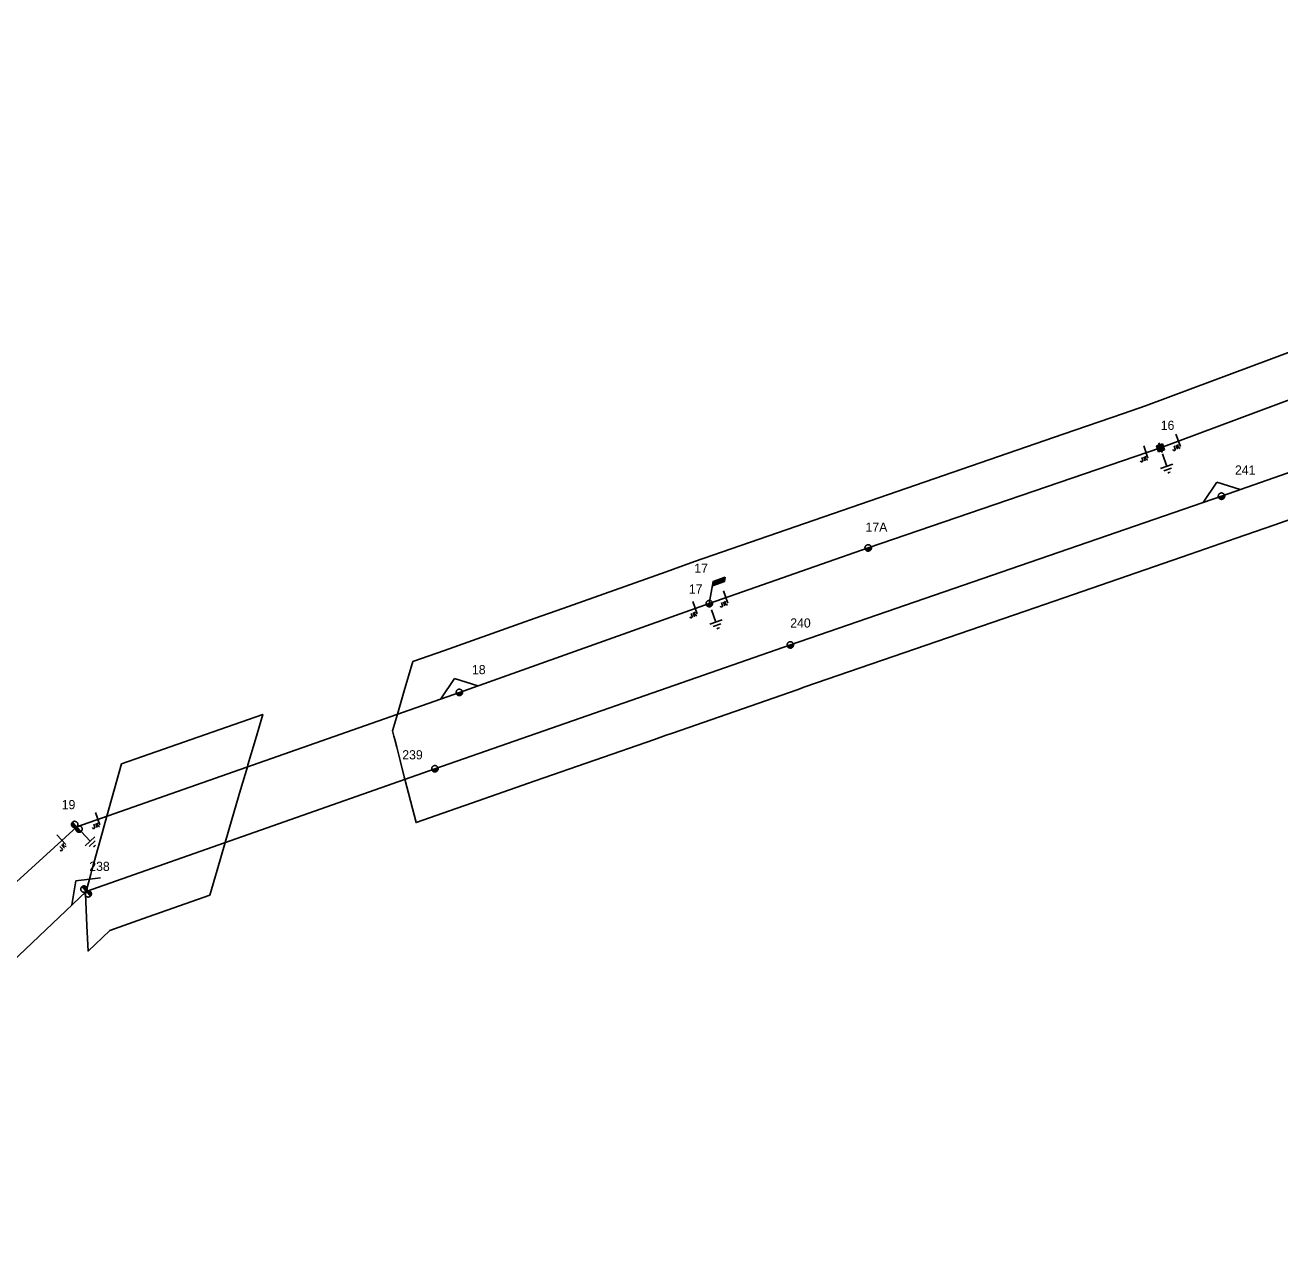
# Model space of a CAD drawing. Extents: x -540879 to -537255, y -1184046 to -1180016.
# Drawn here: x -539234.9 to -538995.4, y -1180859 to -1180626.1 of the extents above; entities that cross this region are included whole.
import ezdxf

# ---------------------------------------------------------------- set-up
doc = ezdxf.new("R2010")
doc.units = 0
for name, color, linetype in [('Default', 7, 'Continuous'), ('Vrstva 1', 7, 'Continuous'), ('Vrstva 11', 7, 'Continuous'), ('Vrstva 12', 7, 'Continuous'), ('Vrstva 13', 7, 'Continuous'), ('Vrstva 14', 7, 'Continuous'), ('Vrstva 15', 7, 'Continuous'), ('Vrstva 18', 7, 'Continuous'), ('Vrstva 2', 7, 'Continuous'), ('Vrstva 35', 7, 'Continuous')]:
    doc.layers.add(name, color=color, linetype=linetype)

# ---------------------------------------------------------------- blocks, each defined once
blk = doc.blocks.new('VN840')
at = {"layer": 'Vrstva 15'}
for points in [[(-0.01, 1.41), (-0.01, -1.09)], [(-1.51, -1.24), (-1.51, -1.15)], [(-1.48, -1.35), (-1.51, -1.24)], [(-1.33, -1.42), (-1.48, -1.35)], [(-1.27, -1.42), (-1.33, -1.42)], [(-1.13, -1.35), (-1.27, -1.42)], [(-1.09, -1.24), (-1.13, -1.35)], [(-1.09, -0.59), (-1.09, -1.24)], [(-0.68, -0.59), (-0.68, -1.42)], [(-0.68, -1.11), (-0.27, -0.59)], [(-0.54, -0.94), (-0.2, -1.42)]]:
    blk.add_lwpolyline(points, dxfattribs=at)
blk = doc.blocks.new('VN860')
at = {"layer": 'Vrstva 15'}
for points in [[(-3.74, 0), (0.01, 2.82)], [(0.01, 2.82), (3.76, 0)]]:
    blk.add_lwpolyline(points, dxfattribs=at)
blk = doc.blocks.new('VN440')
at = {"layer": 'Vrstva 2'}
for points in [[(1.22, 0), (1.21, 0.13), (1.19, 0.25), (1.16, 0.38), (1.11, 0.5), (1.05, 0.61), (0.98, 0.72), (0.9, 0.82), (0.81, 0.91), (0.71, 0.99), (0.6, 1.06), (0.49, 1.12), (0.37, 1.16), (0.25, 1.2), (0.12, 1.22), (-0.01, 1.22), (-0.14, 1.22), (-0.26, 1.2), (-0.39, 1.16), (-0.51, 1.12), (-0.62, 1.06), (-0.73, 0.99), (-0.83, 0.91), (-0.92, 0.82), (-1, 0.72), (-1.07, 0.61), (-1.13, 0.5), (-1.18, 0.38), (-1.21, 0.25), (-1.23, 0.13), (-1.24, 0), (-1.23, -0.13), (-1.21, -0.26), (-1.18, -0.38), (-1.13, -0.5), (-1.07, -0.62), (-1, -0.73), (-0.92, -0.83), (-0.83, -0.92), (-0.73, -1), (-0.62, -1.07), (-0.51, -1.13), (-0.39, -1.17), (-0.26, -1.2), (-0.14, -1.23), (-0.01, -1.23), (0.12, -1.23), (0.25, -1.2), (0.37, -1.17), (0.49, -1.13), (0.6, -1.07), (0.71, -1), (0.81, -0.92), (0.9, -0.83), (0.98, -0.73), (1.05, -0.62), (1.11, -0.5), (1.16, -0.38), (1.19, -0.26), (1.21, -0.13), (1.22, 0)], [(-1.24, 0), (1.22, 0)], [(-1.18, -0.34), (1.1, -0.34)], [(-1.01, -0.63), (0.97, -0.63)], [(-0.74, -0.92), (0.68, -0.92)]]:
    blk.add_lwpolyline(points, dxfattribs=at)
blk = doc.blocks.new('VN810')
at = {"layer": 'Vrstva 14'}
for points in [[(0, -1.25), (0, -3.75)], [(1.25, -3.75), (-1.25, -3.75)], [(0.77, -4.37), (-0.8, -4.37)], [(0, -5), (-0.25, -5)], [(0.27, -5), (0, -5)]]:
    blk.add_lwpolyline(points, dxfattribs=at)
blk = doc.blocks.new('VN450')
at = {"layer": 'Vrstva 2'}
for points in [[(0, 0), (-0.01, 0.13), (-0.03, 0.25), (-0.06, 0.38), (-0.11, 0.5), (-0.16, 0.61), (-0.23, 0.72), (-0.31, 0.82), (-0.4, 0.91), (-0.5, 0.99), (-0.61, 1.06), (-0.72, 1.11), (-0.84, 1.16), (-0.97, 1.19), (-1.09, 1.21), (-1.22, 1.22), (-1.35, 1.21), (-1.47, 1.19), (-1.59, 1.16), (-1.71, 1.11), (-1.83, 1.06), (-1.93, 0.99), (-2.03, 0.91), (-2.12, 0.82), (-2.2, 0.72), (-2.27, 0.61), (-2.33, 0.5), (-2.38, 0.38), (-2.41, 0.25), (-2.43, 0.13), (-2.44, 0), (-2.43, -0.13), (-2.41, -0.25), (-2.38, -0.38), (-2.33, -0.5), (-2.27, -0.61), (-2.2, -0.72), (-2.12, -0.82), (-2.03, -0.91), (-1.93, -0.99), (-1.83, -1.06), (-1.71, -1.11), (-1.59, -1.16), (-1.47, -1.19), (-1.35, -1.21), (-1.22, -1.22), (-1.09, -1.21), (-0.97, -1.19), (-0.84, -1.16), (-0.72, -1.11), (-0.61, -1.06), (-0.5, -0.99), (-0.4, -0.91), (-0.31, -0.82), (-0.23, -0.72), (-0.16, -0.61), (-0.11, -0.5), (-0.06, -0.38), (-0.03, -0.25), (-0.01, -0.13), (0, 0)], [(-2.44, 0), (2.44, 0)], [(2.44, 0), (2.43, 0.13), (2.41, 0.25), (2.38, 0.38), (2.33, 0.5), (2.27, 0.61), (2.2, 0.72), (2.12, 0.82), (2.03, 0.91), (1.94, 0.99), (1.83, 1.06), (1.71, 1.11), (1.6, 1.16), (1.47, 1.19), (1.35, 1.21), (1.22, 1.22), (1.09, 1.21), (0.97, 1.19), (0.84, 1.16), (0.72, 1.11), (0.61, 1.06), (0.5, 0.99), (0.4, 0.91), (0.31, 0.82), (0.23, 0.72), (0.16, 0.61), (0.11, 0.5), (0.06, 0.38), (0.03, 0.25), (0.01, 0.13), (0, 0), (0.01, -0.13), (0.03, -0.25), (0.06, -0.38), (0.11, -0.5), (0.16, -0.61), (0.23, -0.72), (0.31, -0.82), (0.4, -0.91), (0.5, -0.99), (0.61, -1.06), (0.72, -1.11), (0.84, -1.16), (0.97, -1.19), (1.09, -1.21), (1.22, -1.22), (1.35, -1.21), (1.47, -1.19), (1.6, -1.16), (1.71, -1.11), (1.83, -1.06), (1.94, -0.99), (2.03, -0.91), (2.12, -0.82), (2.2, -0.72), (2.27, -0.61), (2.33, -0.5), (2.38, -0.38), (2.41, -0.25), (2.43, -0.13), (2.44, 0)], [(-2.4, -0.31), (-0.04, -0.31)], [(-2.26, -0.61), (-0.17, -0.61)], [(-2.01, -0.92), (-0.42, -0.92)], [(0.04, -0.31), (2.4, -0.31)], [(0.17, -0.61), (2.27, -0.61)], [(0.42, -0.92), (2.02, -0.92)]]:
    blk.add_lwpolyline(points, dxfattribs=at)
blk = doc.blocks.new('VN001')
at = {"layer": 'Default'}
for p, q in [((1.73, 3.03), (4.14, 3.03)), ((1.76, 3.08), (4.17, 3.08)), ((1.79, 3.13), (4.2, 3.13)), ((1.82, 3.18), (4.23, 3.18)), ((1.85, 3.23), (4.26, 3.23)), ((1.87, 3.28), (4.29, 3.28)), ((1.9, 3.33), (4.32, 3.33)), ((1.93, 3.38), (4.35, 3.38)), ((1.96, 3.43), (4.37, 3.43)), ((1.99, 3.48), (4.4, 3.48)), ((2.02, 3.53), (4.43, 3.53)), ((2.05, 3.58), (4.46, 3.58)), ((2.07, 3.63), (4.49, 3.63)), ((2.1, 3.68), (4.52, 3.68)), ((2.13, 3.73), (2.54, 3.73))]:
    blk.add_line(p, q, dxfattribs=at)
blk.add_lwpolyline([(2.13, 3.73), (0, 0)], dxfattribs=at)
blk.add_lwpolyline([(4.55, 3.73), (2.13, 3.73), (1.7, 2.98), (4.12, 2.99)], close=True, dxfattribs=at)
blk = doc.blocks.new('VN470')
at = {"layer": 'Vrstva 2'}
for points in [[(-1.23, 1.22), (1.23, 1.22)], [(-1.23, -1.23), (-1.23, 1.22)], [(-0.92, 0.9), (0.92, 0.9)], [(-0.92, -0.95), (-0.92, 0.9)], [(-0.61, 0.61), (0.61, 0.61)], [(-0.61, -0.62), (-0.61, 0.61)], [(-0.31, -0.27), (-0.31, 0.34)], [(-0.31, 0.34), (0.31, 0.34)], [(0, 1.22), (0, 1.97)], [(0.31, 0.34), (0.31, -0.27)], [(0.61, 0.61), (0.61, -0.62)], [(0.92, 0.9), (0.92, -0.95)], [(1.23, 1.22), (1.23, -1.23)], [(1.23, -1.23), (-1.23, -1.23)], [(0.92, -0.95), (-0.92, -0.95)], [(0.61, -0.62), (-0.61, -0.62)], [(0.31, -0.27), (-0.31, -0.27)], [(0, -1.23), (0, -1.98)]]:
    blk.add_lwpolyline(points, dxfattribs=at)

msp = doc.modelspace()

# ---------------------------------------------------------------- linework, layer by layer
at = {"layer": 'Vrstva 1'}
for points in [[(-538780.03, -1180626.12), (-538848.86, -1180644.11), (-538929.59, -1180673.79), (-539018.19, -1180706.82), (-539073.96, -1180725.94), (-539104.29, -1180736.57)], [(-538881.02, -1180671.8), (-538918.31, -1180685.12), (-539006.53, -1180716.06), (-539088.82, -1180744.46), (-539156.66, -1180768.11), (-539223.23, -1180791.54), (-539293.94, -1180858.74)], [(-539104.29, -1180736.57), (-539151.99, -1180753.53), (-539225, -1180779.19), (-539298.48, -1180846.15), (-539368.99, -1180859.02)]]:
    msp.add_lwpolyline(points, dxfattribs=at)
at = {"layer": 'Vrstva 35'}
msp.add_lwpolyline([(-538987.5, -1180718.39), (-538996.57, -1180721.57), (-539003.73, -1180724.08), (-539012.5, -1180727.11), (-539034.81, -1180734.81), (-539044, -1180737.99), (-539086.03, -1180752.49), (-539087.5, -1180753.01), (-539111.31, -1180761.31), (-539112.5, -1180761.72), (-539114.72, -1180762.5), (-539137.5, -1180770.44), (-539149.69, -1180774.69), (-539153.85, -1180776.14), (-539160.26, -1180778.39), (-539162.38, -1180770.12), (-539162.5, -1180769.66), (-539163.31, -1180766.52), (-539163.96, -1180763.96), (-539164.34, -1180762.5), (-539164.5, -1180761.86), (-539164.75, -1180760.89), (-539163.81, -1180757.69), (-539162.5, -1180753.24), (-539160.85, -1180747.64), (-539154.83, -1180745.52), (-539140.39, -1180740.39), (-539137.5, -1180739.36), (-539132.27, -1180737.5), (-539112.5, -1180730.48), (-539107.13, -1180728.56), (-539036.77, -1180704.21), (-539036.75, -1180704.2), (-539025.26, -1180700.26), (-539021.05, -1180698.82), (-539012.5, -1180695.63), (-538997, -1180689.85), (-538991.87, -1180687.94)], dxfattribs=at)
msp.add_lwpolyline([(-539190.93, -1180762.5), (-539192.34, -1180767.34), (-539192.46, -1180767.76), (-539193.75, -1180772.15), (-539195.4, -1180777.8), (-539196.68, -1180782.2), (-539198.23, -1180787.5), (-539199.62, -1180792.24), (-539212.5, -1180796.78), (-539218.7, -1180798.96), (-539222.85, -1180802.91), (-539223.07, -1180798.07), (-539223.36, -1180791.95), (-539223.24, -1180791.54), (-539222.33, -1180788.26), (-539222.12, -1180787.5), (-539220.47, -1180781.56), (-539219.25, -1180777.17), (-539216.47, -1180767.18), (-539212.5, -1180765.79), (-539203.16, -1180762.51), (-539189.53, -1180757.72)], close=True, dxfattribs=at)

# ---------------------------------------------------------------- block references
at = {"layer": 'Vrstva 11', "rotation": 19.57173893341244}
msp.add_blockref('VN001', (-539104.29, -1180736.57), dxfattribs=at)
at = {"layer": 'Vrstva 13'}
for name, p, xscale, yscale, rotation in [('VN470', (-539018.19, -1180706.82), 0.5000000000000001, 0.4999999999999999, 18.918275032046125), ('VN440', (-539006.53, -1180716.06), 0.5, 0.5, 19.04469726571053), ('VN440', (-539073.96, -1180725.94), 0.5, 0.5, 19.323038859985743), ('VN440', (-539104.29, -1180736.57), 0.49999999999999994, 0.5000000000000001, 19.57211662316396), ('VN440', (-539088.82, -1180744.46), 0.5, 0.5000000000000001, 19.218441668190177), ('VN440', (-539151.99, -1180753.53), 0.5, 0.5, 19.36381108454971), ('VN440', (-539156.66, -1180768.11), 0.5000000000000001, 0.5, 19.388452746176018), ('VN450', (-539225, -1180779.19), 0.49999999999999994, 0.5000000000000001, -46.66834179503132), ('VN450', (-539223.23, -1180791.54), 0.5, 0.5, 131.79668322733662)]:
    msp.add_blockref(name, p, dxfattribs=dict(at, xscale=xscale, yscale=yscale, rotation=rotation))
at = {"layer": 'Vrstva 15'}
for p, rotation in [((-539018.19, -1180706.83), 18.917194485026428), ((-539104.29, -1180736.57), 19.571402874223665), ((-539225, -1180779.19), 42.53507216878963)]:
    msp.add_blockref('VN810', p, dxfattribs=dict(at, rotation=rotation))
at = {"layer": 'Vrstva 18'}
for name, p, rotation in [('VN840', (-539014.76, -1180705.54), 20.44435278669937), ('VN840', (-539020.91, -1180707.76), 18.91836674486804), ('VN860', (-539006.53, -1180716.06), 19.327330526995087), ('VN840', (-539101.13, -1180735.46), 19.32403607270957), ('VN840', (-539106.94, -1180737.52), 19.571680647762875), ('VN860', (-539151.99, -1180753.53), 19.571680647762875), ('VN840', (-539220.95, -1180777.77), 19.36352496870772), ('VN840', (-539227.84, -1180781.77), 42.345491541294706), ('VN860', (-539223.23, -1180791.54), 43.540738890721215)]:
    msp.add_blockref(name, p, dxfattribs=dict(at, rotation=rotation))

# ---------------------------------------------------------------- texts
at = {"layer": 'Vrstva 12'}
msp.add_text('17', height=1.75, dxfattribs=at).set_placement((-539107.15, -1180730.7))
at = {"layer": 'Vrstva 14'}
for s, p in [('16', (-539018.13, -1180703.41)), ('241', (-539003.96, -1180711.95)), ('17A', (-539074.47, -1180722.85)), ('17', (-539108.2, -1180734.67)), ('240', (-539088.84, -1180741.15)), ('18', (-539149.59, -1180750.05)), ('239', (-539162.89, -1180766.32)), ('19', (-539227.89, -1180775.83)), ('238', (-539222.63, -1180787.62))]:
    msp.add_text(s, height=1.75, dxfattribs=at).set_placement(p)

doc.saveas('drawing.dxf')
